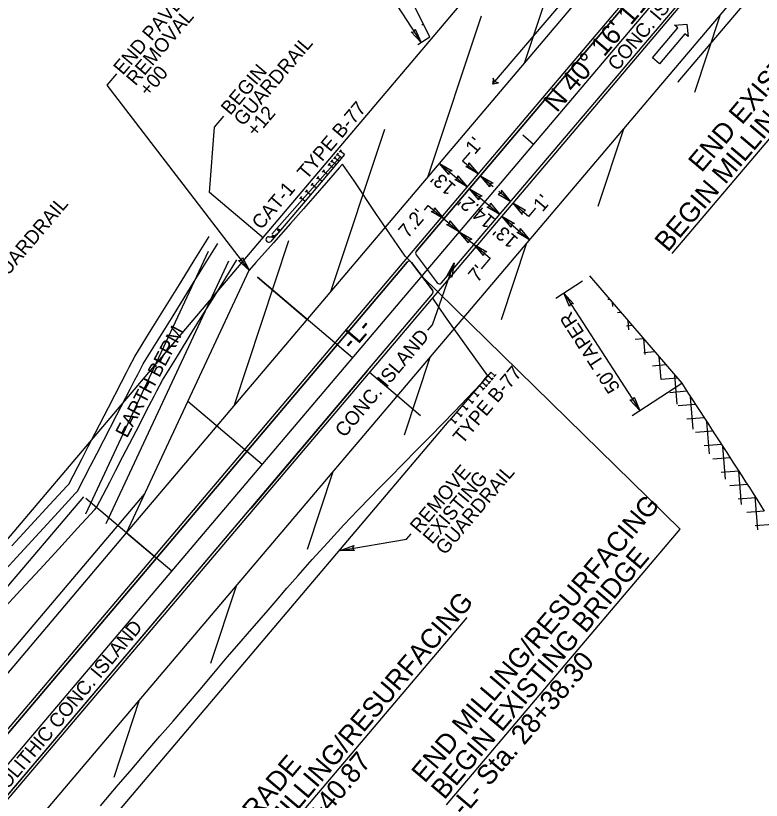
# Model space of a CAD drawing. Extents: x 1761082 to 1764358, y 421907 to 425434.
# Drawn here: x 1762337.6 to 1762604.1, y 423126 to 423406.5 of the extents above; entities that cross this region are included whole.
import ezdxf

# ---------------------------------------------------------------- set-up
doc = ezdxf.new("R2010")
doc.units = 0
for name, color, linetype in [('MARK HOOKS CENTER LEFT TURN ARROW CELL', 7, 'Continuous'), ('MARK HOOKS CENTER STRAIGHT LEFT TURN ARROW CELL', 7, 'Continuous'), ('MARK HOOKS STRAIGHT RIGHT TURN ARROW CELL', 7, 'Continuous'), ('MARK STRAIGHT RIGHT ARROW CELL', 7, 'Continuous'), ('MARK UTURN ARROW CELL', 7, 'Continuous'), ('Prop Berm Ditch Flow Line', 7, 'Continuous'), ('Prop Conc 4in Sidewalk', 7, 'Continuous'), ('Prop Drainage Ditch Boundaries', 7, 'Continuous'), ('Prop Mkg 3ft Min Skp 3ft Wide White', 7, 'Continuous'), ('Prop Mkg 3ft Min Skp 9ft Wide White', 7, 'Continuous'), ('Prop Mkg Skp Wht', 7, 'Continuous'), ('Prop Mkg Solid White Diagonals', 7, 'Continuous'), ('Prop Mkg Solid White Lane Line', 7, 'Continuous'), ('Prop Mkg Solid White Multiple Diagonals V8i', 7, 'Continuous'), ('Prop Mkg Solid White Stop Bar', 7, 'Continuous'), ('Prop Mkg Solid White Wide Lane Line', 7, 'Continuous'), ('Prop Mkg Solid Yel Skip LT', 7, 'Continuous'), ('Prop Mkg Solid Yel Skip RT', 7, 'Continuous'), ('Prop Mkg Solid Yellow Diagonals', 7, 'Continuous'), ('Prop Mkg Solid Yellow Lane Line', 7, 'Continuous'), ('Prop Mkg Yld Lin', 7, 'Continuous'), ('Prop Structure Anchor Unit CELL', 7, 'Continuous'), ('Scratch_Level_0', 7, 'Continuous'), ('Scratch_Level_1', 7, 'Continuous'), ('Text', 7, 'Continuous')]:
    doc.layers.add(name, color=color, linetype=linetype)

msp = doc.modelspace()

# ---------------------------------------------------------------- linework, layer by layer
at = {"layer": 'MARK HOOKS CENTER STRAIGHT LEFT TURN ARROW CELL'}
for p, q in [((1762522.67, 423360.49), (1762518.85, 423363.73)), ((1762458.03, 423284.19), (1762454.21, 423287.43)), ((1762393.39, 423207.89), (1762389.58, 423211.12))]:
    msp.add_line(p, q, dxfattribs=at)
at = {"layer": 'MARK STRAIGHT RIGHT ARROW CELL'}
msp.add_line((1761294.53, 421910.78), (1762672.97, 423537.92), dxfattribs=at)
at = {"layer": 'MARK UTURN ARROW CELL'}
for points in [[(1762572.31, 423321.5), (1762658.86, 423423.66), (1762630.42, 423487.69)], [(1762491.66, 423124.36), (1762575.15, 423222.91), (1762482.79, 423313.42)], [(1762290.53, 423086.48), (1762412.19, 423088.84), (1762499.02, 423191.34)]]:
    msp.add_lwpolyline(points, dxfattribs=at)
at = {"layer": 'Prop Berm Ditch Flow Line'}
msp.add_lwpolyline([(1762332.67, 423193.8), (1762339.44, 423201.17), (1762346.22, 423208.54), (1762352.99, 423215.91), (1762359.76, 423223.28), (1762365.81, 423229.86), (1762366.53, 423230.65), (1762371.25, 423239.76), (1762373.45, 423244.02), (1762375.96, 423248.87), (1762380.67, 423257.99), (1762385.38, 423267.1), (1762387.12, 423270.46), (1762388.11, 423272.38), (1762390.1, 423276.21), (1762395.42, 423284.81), (1762400.74, 423293.41), (1762406.07, 423302), (1762407.95, 423305.04), (1762411.39, 423310.6), (1762416.71, 423319.19)], dxfattribs=at)
at = {"layer": 'Prop Conc 4in Sidewalk'}
for p, q in [((1762482.76, 423403.34), (1762483.43, 423403.39)), ((1762545.46, 423310.11), (1762545.44, 423310.41)), ((1762546, 423309.75), (1762545.76, 423309.73)), ((1762550.02, 423305.06), (1762549.33, 423305)), ((1762551.11, 423302.53), (1762550.99, 423303.93)), ((1762554.03, 423300.38), (1762552.68, 423300.26)), ((1762556.81, 423294.17), (1762556.54, 423297.45)), ((1762558.05, 423295.69), (1762555.91, 423295.51)), ((1762562.06, 423291.01), (1762559.04, 423290.76)), ((1762562.56, 423285.31), (1762562.1, 423290.97)), ((1762566.08, 423286.32), (1762562.12, 423285.99)), ((1762568.32, 423276.43), (1762567.65, 423284.49)), ((1762570.09, 423281.64), (1762565.21, 423281.23)), ((1762574.07, 423267.56), (1762573.2, 423278)), ((1762574.11, 423276.95), (1762568.29, 423276.47)), ((1762577.56, 423272.22), (1762571.38, 423271.71)), ((1762579.82, 423258.68), (1762578.86, 423270.21)), ((1762580.65, 423267.46), (1762574.46, 423266.95)), ((1762583.74, 423262.7), (1762577.55, 423262.18)), ((1762585.57, 423249.79), (1762584.62, 423261.34)), ((1762586.83, 423257.94), (1762580.63, 423257.42)), ((1762589.91, 423253.17), (1762583.72, 423252.66)), ((1762591.33, 423240.79), (1762590.37, 423252.47)), ((1762593, 423248.41), (1762586.79, 423247.9)), ((1762596.09, 423243.65), (1762589.84, 423243.13)), ((1762597.1, 423231.72), (1762596.12, 423243.6)), ((1762599.15, 423238.89), (1762592.88, 423238.37)), ((1762602.17, 423234.12), (1762595.91, 423233.6)), ((1762602.87, 423222.65), (1762601.88, 423234.58)), ((1762605.18, 423229.35), (1762598.94, 423228.84)), ((1762608.19, 423224.58), (1762601.97, 423224.07))]:
    msp.add_line(p, q, dxfattribs=at)
at = {"layer": 'Prop Drainage Ditch Boundaries'}
for points in [[(1762332.58, 423206.99), (1762339.35, 423214.36), (1762346.12, 423221.73), (1762352.89, 423229.09), (1762358.94, 423235.67), (1762359.67, 423236.46), (1762364.38, 423245.58), (1762366.58, 423249.84), (1762369.09, 423254.69), (1762373.8, 423263.8), (1762378.52, 423272.92), (1762380.26, 423276.28), (1762381.25, 423278.19), (1762383.23, 423282.03), (1762388.55, 423290.63), (1762393.88, 423299.22), (1762399.2, 423307.82), (1762401.09, 423310.86), (1762404.52, 423316.42), (1762409.85, 423325.01)], [(1762336.3, 423216.94), (1762343.07, 423224.31), (1762349.84, 423231.68), (1762355.89, 423238.26), (1762356.61, 423239.05), (1762361.33, 423248.16), (1762363.53, 423252.43), (1762366.04, 423257.28), (1762370.75, 423266.39), (1762375.47, 423275.5), (1762377.2, 423278.87), (1762378.19, 423280.78), (1762380.18, 423284.62), (1762385.5, 423293.21), (1762390.83, 423301.81), (1762396.15, 423310.4), (1762398.03, 423313.45), (1762401.47, 423319), (1762406.8, 423327.6)]]:
    msp.add_lwpolyline(points, dxfattribs=at)
at = {"layer": 'Prop Mkg 3ft Min Skp 3ft Wide White'}
msp.add_line((1761294.53, 421910.78), (1762672.97, 423537.92), dxfattribs=at)
at = {"layer": 'Prop Mkg 3ft Min Skp 9ft Wide White'}
for p, q in [((1762440.32, 423339.37), (1762432.24, 423329.83)), ((1762356.81, 423101.28), (1762492.62, 423261.6))]:
    msp.add_line(p, q, dxfattribs=at)
at = {"layer": 'Prop Mkg Skp Wht'}
for p, q in [((1762377.21, 423221.6), (1762421.06, 423315.51)), ((1762276.97, 423103.27), (1762377.21, 423221.6))]:
    msp.add_line(p, q, dxfattribs=at)
for points in [[(1762476.88, 423320.57), (1762466.4, 423335.74), (1762458.61, 423347.43), (1762454.45, 423353.47)], [(1762476.88, 423320.57), (1762479.08, 423318.3)], [(1762486.57, 423305.51), (1762491.19, 423298.87), (1762499.19, 423287.55), (1762506.31, 423277.74)]]:
    msp.add_lwpolyline(points, dxfattribs=at)
at = {"layer": 'Prop Mkg Solid White Diagonals'}
for p, q in [((1762623.68, 423490.87), (1762480.79, 423322.2)), ((1762489.87, 423310.95), (1762632.52, 423479.34)), ((1762480.76, 423320.95), (1762488.31, 423310.99)), ((1762477.52, 423318.34), (1762279.46, 423084.55)), ((1762486.64, 423308.35), (1762479.08, 423318.3))]:
    msp.add_line(p, q, dxfattribs=at)
msp.add_lwpolyline([(1762299.17, 423085.85), (1762463.37, 423279.67), (1762486.6, 423307.09)], dxfattribs=at)
for centre, start, end in [((1762481.55, 423321.55), 139.7301, 217.1916), ((1762478.29, 423317.7), 37.1916, 139.7301), ((1762489.11, 423311.6), 217.1916, 319.7301), ((1762485.84, 423307.74), 319.7301, 37.1916)]:
    msp.add_arc(centre, 1, start, end, dxfattribs=at)
at = {"layer": 'Prop Mkg Solid White Lane Line'}
for p, q in [((1762480.79, 423322.2), (1762623.68, 423490.87)), ((1762279.46, 423084.55), (1762477.52, 423318.34)), ((1762479.08, 423318.3), (1762486.64, 423308.35)), ((1762299.17, 423085.85), (1762486.6, 423307.09)), ((1762463.37, 423279.67), (1762421.71, 423230.33))]:
    msp.add_line(p, q, dxfattribs=at)
for centre, start, end in [((1762481.55, 423321.55), 139.7301, 217.1916), ((1762478.29, 423317.7), 37.1916, 139.7301), ((1762485.84, 423307.74), 319.7301, 37.1916)]:
    msp.add_arc(centre, 1, start, end, dxfattribs=at)
at = {"layer": 'Prop Mkg Solid White Multiple Diagonals V8i'}
for p, q in [((1762270.77, 423143.91), (1762579.6, 423508.45)), ((1762429.23, 423328.35), (1762453.78, 423356.12)), ((1762362.72, 423228.37), (1762406.57, 423322.28)), ((1762369.97, 423224.98), (1762413.82, 423318.89)), ((1762458.03, 423284.19), (1762424.03, 423313)), ((1762425.71, 423246.04), (1762399.14, 423268.55)), ((1762261.71, 423116.2), (1762361.95, 423234.52)), ((1762389.58, 423211.12), (1762362.67, 423233.92))]:
    msp.add_line(p, q, dxfattribs=at)
at = {"layer": 'Prop Mkg Solid White Stop Bar'}
for p, q in [((1762485.64, 423398.95), (1762463.2, 423443.99)), ((1762542.75, 423313.54), (1762575.7, 423275.09)), ((1762291.07, 423126.1), (1762383.65, 423235.38))]:
    msp.add_line(p, q, dxfattribs=at)
for points in [[(1762454.45, 423353.47), (1762453.21, 423352.06), (1762449.41, 423347.69), (1762443.85, 423341.3), (1762440.45, 423337.41), (1762435.85, 423332.19), (1762429.73, 423325.28), (1762423.51, 423318.26), (1762421.06, 423315.51)], [(1762367.91, 423123.95), (1762374.31, 423131.46), (1762378.51, 423136.42), (1762384.89, 423143.86), (1762389.17, 423148.83), (1762393.87, 423154.28), (1762398.65, 423159.87), (1762403.52, 423165.6), (1762408.49, 423171.47), (1762413.23, 423177.09), (1762417.47, 423182.05), (1762421.18, 423186.35), (1762427.12, 423193.12), (1762431.45, 423198.1), (1762434.59, 423201.78), (1762438.57, 423206.35), (1762443.64, 423212.06), (1762449.18, 423218.19), (1762454.92, 423224.44), (1762459.88, 423229.73), (1762464.4, 423234.4), (1762467.55, 423237.59), (1762471.45, 423241.54), (1762476.11, 423246.23), (1762481.05, 423251.22), (1762485.78, 423256.03), (1762490.3, 423260.68), (1762494.61, 423265.15), (1762501.21, 423272.07), (1762504.19, 423275.27), (1762505.55, 423276.86), (1762506.31, 423277.74)], [(1762575.7, 423275.09), (1762578.16, 423271.29), (1762579.52, 423269.19), (1762580.88, 423267.1), (1762582.24, 423265), (1762583.6, 423262.9), (1762584.96, 423260.8), (1762586.32, 423258.71), (1762587.68, 423256.61), (1762589.04, 423254.51), (1762590.4, 423252.42), (1762591.76, 423250.32), (1762593.12, 423248.22), (1762594.48, 423246.13), (1762595.84, 423244.03), (1762597.19, 423241.95), (1762598.52, 423239.87), (1762599.85, 423237.79), (1762601.18, 423235.7), (1762602.51, 423233.59), (1762603.84, 423231.48), (1762605.17, 423229.37)]]:
    msp.add_lwpolyline(points, dxfattribs=at)
at = {"layer": 'Prop Mkg Solid White Wide Lane Line'}
for p, q in [((1762574.37, 423382.84), (1762668.14, 423493.53)), ((1762508.22, 423382.12), (1762600.89, 423491.5))]:
    msp.add_line(p, q, dxfattribs=at)
msp.add_lwpolyline([(1762508.22, 423382.12), (1762510.18, 423382.54), (1762508.87, 423382.88), (1762508.32, 423384.12)], close=True, dxfattribs=at)
for centre in [(1762508.22, 423382.12), (1762574.37, 423382.84)]:
    msp.add_circle(centre, 0.0417, dxfattribs=at)
at = {"layer": 'Prop Mkg Solid Yel Skip RT'}
for p, q in [((1762455.3, 423438.86), (1762482.5, 423396.91)), ((1762481.39, 423396.19), (1762485.64, 423398.95)), ((1762489.12, 423353.69), (1762499.04, 423345.29)), ((1762503.73, 423349.28), (1762508.24, 423345.46)), ((1762499.8, 423344.64), (1762510.64, 423335.46)), ((1762514.57, 423340.1), (1762510.35, 423343.67)), ((1762511.4, 423334.82), (1762521.32, 423326.42)), ((1762530.74, 423305.52), (1762540.2, 423311.66)), ((1762533.49, 423307.31), (1762560.7, 423265.35)), ((1762557.94, 423263.57), (1762575.7, 423275.09))]:
    msp.add_line(p, q, dxfattribs=at)
for points in [[(1762421.06, 423315.51), (1762370.36, 423381.72), (1762373.72, 423385.69)], [(1762426.17, 423326.91), (1762406.89, 423343.25), (1762408.65, 423366.64), (1762412.01, 423370.6)], [(1762499.9, 423357.63), (1762497.38, 423354.66), (1762502.97, 423349.93)], [(1762523.43, 423337.69), (1762520.92, 423334.72), (1762515.33, 423339.45)], [(1762483.73, 423337.01), (1762485.07, 423338.59), (1762496.16, 423329.2)], [(1762496.16, 423329.2), (1762507.24, 423319.81), (1762504.05, 423316.04)], [(1762484.94, 423294.07), (1762486.57, 423295.99), (1762494.36, 423318.17)], [(1762453.58, 423215.25), (1762477.31, 423219.33), (1762478.97, 423221.29)]]:
    msp.add_lwpolyline(points, dxfattribs=at)
at = {"layer": 'Prop Mkg Solid Yellow Diagonals'}
for p, q in [((1762565.25, 423391.43), (1762574.29, 423402.12)), ((1762573.14, 423403.09), (1762577.54, 423403.5)), ((1762574.29, 423402.12), (1762573.14, 423403.09)), ((1762577.54, 423403.5), (1762577.96, 423399.03)), ((1762576.81, 423399.99), (1762567.77, 423389.3)), ((1762577.96, 423399.03), (1762576.81, 423399.99)), ((1762567.77, 423389.3), (1762565.25, 423391.43))]:
    msp.add_line(p, q, dxfattribs=at)
at = {"layer": 'Prop Mkg Solid Yellow Lane Line'}
for points in [[(1762480.46, 423401.67), (1762482.5, 423396.91), (1762478.95, 423400.72), (1762480.06, 423400.67)], [(1762492.45, 423349.72), (1762489.12, 423353.69), (1762493.62, 423351.07), (1762492.54, 423350.8)], [(1762499.64, 423353.9), (1762502.97, 423349.93), (1762498.47, 423352.55), (1762499.55, 423352.82)], [(1762495.71, 423349.26), (1762499.04, 423345.29), (1762494.54, 423347.91), (1762495.62, 423348.18)], [(1762507.06, 423345.31), (1762503.73, 423349.28), (1762508.23, 423346.66), (1762507.15, 423346.38)], [(1762503.13, 423340.67), (1762499.8, 423344.64), (1762504.31, 423342.02), (1762503.22, 423341.75)], [(1762510.1, 423342.73), (1762514.57, 423340.1), (1762511.24, 423344.11), (1762511.15, 423343)], [(1762507.31, 423339.43), (1762510.64, 423335.46), (1762506.14, 423338.09), (1762507.22, 423338.36)], [(1762519.79, 423336.83), (1762515.33, 423339.45), (1762518.66, 423335.45), (1762518.75, 423336.56)], [(1762487.34, 423337.82), (1762490.66, 423333.85), (1762486.16, 423336.48), (1762487.24, 423336.75)], [(1762514.73, 423330.85), (1762511.4, 423334.82), (1762515.9, 423332.19), (1762514.82, 423331.92)], [(1762492.83, 423333.17), (1762496.16, 423329.2), (1762491.65, 423331.82), (1762492.74, 423332.09)], [(1762499.48, 423325.23), (1762496.16, 423329.2), (1762500.66, 423326.57), (1762499.57, 423326.3)], [(1762517.99, 423330.38), (1762521.32, 423326.42), (1762516.82, 423329.04), (1762517.9, 423329.31)], [(1762504.82, 423320.7), (1762501.5, 423324.67), (1762506, 423322.05), (1762504.91, 423321.78)], [(1762418.66, 423320.1), (1762421.06, 423315.51), (1762417.22, 423319.03), (1762418.34, 423319.07)], [(1762491.84, 423313.65), (1762494.36, 423318.17), (1762493.52, 423313.03), (1762492.88, 423313.95)], [(1762535.53, 423302.55), (1762533.49, 423307.31), (1762537.05, 423303.5), (1762535.93, 423303.55)], [(1762558.66, 423270.11), (1762560.7, 423265.35), (1762557.14, 423269.17), (1762558.26, 423269.11)], [(1762458.76, 423215.25), (1762453.58, 423215.25), (1762458.48, 423217.01), (1762457.99, 423216.01)]]:
    msp.add_lwpolyline(points, close=True, dxfattribs=at)
at = {"layer": 'Prop Mkg Yld Lin'}
for p, q in [((1762429.16, 423327.44), (1762429.61, 423327.98)), ((1762429.61, 423327.98), (1762430.23, 423327.46)), ((1762429.78, 423326.92), (1762429.61, 423327.98)), ((1762429.7, 423327.45), (1762431.23, 423328.64)), ((1762432.24, 423329.83), (1762429.95, 423327.12)), ((1762431.17, 423329.82), (1762431.62, 423330.35)), ((1762432.24, 423329.83), (1762431.17, 423329.82)), ((1762431.79, 423329.29), (1762431.17, 423329.82)), ((1762431.62, 423330.35), (1762432.24, 423329.83)), ((1762431.79, 423329.29), (1762431.62, 423330.35)), ((1762432.24, 423329.83), (1762431.79, 423329.29)), ((1762428.14, 423327.44), (1762429.24, 423327.38)), ((1762429.95, 423327.12), (1762428.84, 423325.81)), ((1762430.23, 423327.46), (1762429.16, 423327.44)), ((1762429.78, 423326.92), (1762429.16, 423327.44)), ((1762430.23, 423327.46), (1762429.78, 423326.92)), ((1762429.86, 423327.02), (1762429.95, 423327.12))]:
    msp.add_line(p, q, dxfattribs=at)
msp.add_ellipse((1762428.08, 423326.46), major_axis=(0.758, -0.642), ratio=0.995379, start_param=2.210226, end_param=6.283185, dxfattribs=at)
at = {"layer": 'Prop Structure Anchor Unit CELL'}
for p, q in [((1762455.11, 423356.82), (1762440.32, 423339.37)), ((1762451.93, 423356.17), (1762451.19, 423355.29)), ((1762452.94, 423357.36), (1762452.2, 423356.48)), ((1762454.1, 423355.63), (1762452.57, 423356.92)), ((1762453.95, 423358.55), (1762453.21, 423357.68)), ((1762455.11, 423356.82), (1762453.58, 423358.11)), ((1762449.91, 423353.78), (1762449.17, 423352.91)), ((1762451.07, 423352.05), (1762449.54, 423353.34)), ((1762450.92, 423354.97), (1762450.18, 423354.1)), ((1762452.08, 423353.24), (1762450.55, 423354.54)), ((1762453.09, 423354.44), (1762451.56, 423355.73)), ((1762447.89, 423351.4), (1762447.15, 423350.52)), ((1762449.05, 423349.67), (1762447.52, 423350.96)), ((1762445.87, 423349.01), (1762445.13, 423348.14)), ((1762447.03, 423347.28), (1762445.5, 423348.58)), ((1762443.85, 423346.63), (1762443.11, 423345.75)), ((1762445.01, 423344.9), (1762443.48, 423346.19)), ((1762439.81, 423341.86), (1762439.07, 423340.99)), ((1762441.83, 423344.24), (1762441.09, 423343.37)), ((1762442.99, 423342.51), (1762441.46, 423343.81)), ((1762440.97, 423340.13), (1762439.44, 423341.42)), ((1762507.41, 423279.05), (1762492.62, 423261.6)), ((1762506.4, 423277.86), (1762507.93, 423276.56)), ((1762507.41, 423279.05), (1762508.94, 423277.75)), ((1762509.31, 423278.19), (1762508.57, 423277.32)), ((1762504.38, 423275.47), (1762505.91, 423274.18)), ((1762505.39, 423276.66), (1762506.92, 423275.37)), ((1762506.28, 423274.62), (1762505.54, 423273.74)), ((1762507.29, 423275.81), (1762506.55, 423274.93)), ((1762508.3, 423277), (1762507.56, 423276.13)), ((1762501.35, 423271.9), (1762502.88, 423270.6)), ((1762503.37, 423274.28), (1762504.9, 423272.99)), ((1762505.27, 423273.42), (1762504.53, 423272.55)), ((1762499.33, 423269.51), (1762500.86, 423268.22)), ((1762503.25, 423271.04), (1762502.51, 423270.17)), ((1762497.31, 423267.13), (1762498.84, 423265.84)), ((1762499.21, 423266.27), (1762498.47, 423265.4)), ((1762501.23, 423268.66), (1762500.49, 423267.78)), ((1762495.29, 423264.75), (1762496.82, 423263.45)), ((1762497.19, 423263.89), (1762496.45, 423263.02)), ((1762493.27, 423262.36), (1762494.79, 423261.07)), ((1762495.17, 423261.51), (1762494.42, 423260.63))]:
    msp.add_line(p, q, dxfattribs=at)
at = {"layer": 'Scratch_Level_0'}
for p, q in [((1762299.96, 423085.24), (1762664.95, 423516.07)), ((1762278.7, 423085.2), (1762626.96, 423496.29)), ((1762339.89, 423112.25), (1762662.64, 423493.23)), ((1762377.21, 423221.6), (1762603.25, 423488.41)), ((1762538.53, 423447.16), (1762519.41, 423389.45)), ((1762503.95, 423406.39), (1762484.81, 423348.6)), ((1762589.43, 423406.81), (1762580.22, 423379.01)), ((1762469.42, 423365.76), (1762450.2, 423307.75)), ((1762554.82, 423365.96), (1762545.66, 423338.3)), ((1762435.18, 423326.01), (1762415.6, 423266.9)), ((1762520.22, 423325.11), (1762511.13, 423297.7)), ((1762424.03, 423313), (1762441.85, 423297.9)), ((1762485.61, 423284.27), (1762476.43, 423256.54)), ((1762464.13, 423279.02), (1762474.05, 423270.62)), ((1762474.05, 423270.62), (1762482.37, 423263.57)), ((1762451.01, 423243.42), (1762441.79, 423215.61)), ((1762377.21, 423221.6), (1762387.13, 423213.19)), ((1762416.4, 423202.57), (1762407.22, 423174.85)), ((1762381.8, 423161.72), (1762372.66, 423134.13))]:
    msp.add_line(p, q, dxfattribs=at)
at = {"layer": 'Scratch_Level_1'}
msp.add_line((1762508.22, 423382.12), (1762600.89, 423491.5), dxfattribs=at)
msp.add_lwpolyline([(1762508.22, 423382.12), (1762510.18, 423382.54), (1762508.87, 423382.88), (1762508.32, 423384.12)], close=True, dxfattribs=at)
msp.add_circle((1762508.22, 423382.12), 0.0417, dxfattribs=at)
at = {"layer": 'Text'}
for p, q in [((1762489.87, 423310.95), (1762632.52, 423479.34)), ((1762480.76, 423320.95), (1762488.31, 423310.99))]:
    msp.add_line(p, q, dxfattribs=at)
msp.add_arc((1762489.11, 423311.6), 1, 217.1916, 319.7301, dxfattribs=at)

# ---------------------------------------------------------------- texts
at = {"layer": 'MARK HOOKS CENTER LEFT TURN ARROW CELL'}
msp.add_text('N 40%%d 16\' 11.6" E', height=7, rotation=49.7301, dxfattribs=at).set_placement((1762531.03, 423371.58))
at = {"layer": 'MARK HOOKS STRAIGHT RIGHT TURN ARROW CELL'}
msp.add_text('-L-', height=7, rotation=49.7301, dxfattribs=at).set_placement((1762458.03, 423286.38))
at = {"layer": 'MARK UTURN ARROW CELL'}
for s, p in [('BEGIN MILLING/RESURFACING', (1762570.73, 423321.7)), ('END EXISTING BRIDGE', (1762582.78, 423350.13)), ('END MILLING/RESURFACING', (1762483.83, 423131.81)), ('BEGIN EXISTING BRIDGE', (1762490.83, 423125.88)), ('BEGIN MILLING/RESURFACING', (1762411.16, 423089.99)), ('-L- Sta. 28+38.30', (1762497.83, 423119.95)), ('-L- Sta. 25+40.87', (1762418.16, 423084.06)), ('END GRADE', (1762404.16, 423095.92))]:
    msp.add_text(s, height=7, rotation=49.7301, dxfattribs=at).set_placement(p)
at = {"layer": 'Prop Mkg Solid Yel Skip LT'}
for s, rotation, p in [('END PAVEMENT', 49.7301, (1762375.9, 423385.03)), ('CONC. ISLAND', 49.8913, (1762552.6, 423386.45)), ('REMOVAL', 49.7301, (1762380.48, 423381.15)), ('GUARDRAIL', 49.7301, (1762418.9, 423366.75)), ('+00', 49.7301, (1762385.06, 423377.27)), ('BEGIN', 49.7301, (1762414.33, 423370.63)), ('+12', 49.7301, (1762423.48, 423362.87)), ("1'", 49.7301, (1762501.71, 423356.59)), ("13'", 139.7301, (1762495.32, 423345.57)), ("14.2'", 139.7301, (1762509.31, 423333.72)), ("1'", 49.7301, (1762525.93, 423336.08)), ('EXISTING GUARDRAIL', 49.7301, (1762310.12, 423284.13)), ("7.2'", 49.7301, (1762477.78, 423326.65)), ("13'", 139.7301, (1762517.6, 423326.69)), ("7'", 49.7301, (1762502.7, 423310.84)), ("50' TAPER", 122.9603, (1762553.84, 423273.52)), ('EARTH BERM', 61.9433, (1762377.4, 423255.22)), ('CONC. ISLAND', 49.8913, (1762455.11, 423255.39)), ('REMOVE', 49.7301, (1762481.9, 423221.14)), ('GUARDRAIL', 49.7301, (1762491.06, 423213.38)), ('EXISTING', 49.7301, (1762486.48, 423217.26)), ('MONOLITHIC CONC. ISLAND', 50.1302, (1762324.67, 423117.59))]:
    msp.add_text(s, height=5, rotation=rotation, dxfattribs=at).set_placement(p)
at = {"layer": 'Prop Mkg Yld Lin'}
msp.add_text('CAT-1', height=5, rotation=49.7301, dxfattribs=at).set_placement((1762425.36, 423329.7))
at = {"layer": 'Prop Structure Anchor Unit CELL'}
for p in [(1762441.61, 423347.6), (1762497.29, 423253.03)]:
    msp.add_text('TYPE B-77', height=5, rotation=49.7301, dxfattribs=at).set_placement(p)

doc.saveas('drawing.dxf')
